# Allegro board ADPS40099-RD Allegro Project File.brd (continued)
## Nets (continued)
UNNAMED_3_ADMAX77857_I197_BST1: C17.2(N2) U3.A3
UNNAMED_3_ADMAX77857_I197_BST2: C21.1 U3.E3
UNNAMED_3_ADMAX77857_I197_EN1: P17.2 U3.B2 U3.B3
UNNAMED_3_ADMAX77857_I197_IN1: C84.1 C85.1 IN_U3.1(N1) P35.1 R76.1 U3.A4 U3.A5 U3.A6 U3.B4
UNNAMED_3_ADMAX77857_I197_LX11: C17.1 L1.2(N2) U3.A7 U3.B5 U3.B6 U3.B7
UNNAMED_3_ADMAX77857_I197_POKB: R27.2(N2) U3.C2
UNNAMED_3_ADMAX77857_I197_SEL: R77.1 U3.D1
UNNAMED_3_CN3P_I185_N1: P17.1 R76.2(N2)
UNNAMED_5_ADLTC3621V2_I158_FB: C107.2(N2) R91.1 R92.1 R102.2(N2) U9.5
UNNAMED_5_ADLTC3621V2_I158_INTVCC: C106.1 P41.2(N2) R99.2(N2) R100.1 U9.6
UNNAMED_5_ADLTC3621V2_I158_PGOOD: R99.1 U9.4
UNNAMED_5_ADLTC3621V2_I158_RUN: P39.2 U9.3
UNNAMED_5_ADLTC3621V2_I158_SW: L8.1 U9.1
UNNAMED_5_ADMAX1722X_I186_EN: R103.2(N2) U10.6
UNNAMED_5_ADMAX1722X_I186_LX: L9.2(N2) U10.2
UNNAMED_5_ADMAX1722X_I186_SEL: R45.1 U10.4(SEL)
UNNAMED_5_ADMAX38889_I125_BKB: R95.1 U5.4
UNNAMED_5_ADMAX38889_I125_CAP: C73.P C74.1 L7.1 R51.1 U5.2 U5.5 VCAP.1(N1)
UNNAMED_5_ADMAX38889_I125_FBCH: C88.1 R52.2(N2) R53.1 U5.10
UNNAMED_5_ADMAX38889_I125_FBCR: R51.2(N2) R52.1 U5.9
UNNAMED_5_ADMAX38889_I125_FBS: R71.2(N2) R72.1 U5.11
UNNAMED_5_ADMAX38889_I125_ISET: R57.1 U5.12
UNNAMED_5_ADMAX38889_I125_LX1: L7.2(N2) U5.6 U5.7 U5.8
UNNAMED_5_ADMAX38889_I125_RDY: R97.2(N2) RDY.1(N1) U5.3
UNNAMED_5_CAP_I104_N1: C91.1 C92.1 C97.1 C98.1 C105.1 P19.2(N2) R69.1 R71.1 R96.1 R97.1 U5.13 U5.14(SYS_2)
UNNAMED_5_CAP_I119_N1: BKB.1(N1) C76.1 R95.2(N2) R96.2(N2)
UNNAMED_5_CN2P_I181_N1: C95.1 L9.1 P46.1 P48.2(N2) P49.2(N2) R103.1 U10.5
UNNAMED_5_NC2P_I157_N1: P38.1 R92.2(N2)
UNNAMED_5_NC2P_I163_N1: P41.1 P42.2(N2) R100.2(N2) R101.1 U9.7
UNNAMED_5_NC2P_I176_N1: P28.1 R91.2(N2)
UNNAMED_5_RES_I103_N2: R69.2(N2) R98.1
UNNAMED_6_CAP_I13_N2: C117.2(N2) R117.1 U14.7(WP)
UNNAMED_6_IC24XX32AV2_I1_A0: R111.2(N2) R112.1 U14.1
UNNAMED_6_IC24XX32AV2_I1_A1: R109.2(N2) R110.1 U14.2
UNNAMED_6_IC24XX32AV2_I1_A2: R61.2(N2) R62.1 U14.3
UNNAMED_6_IC24XX32AV2_I1_SCL: R113.1 U14.6
UNNAMED_6_IC24XX32AV2_I1_SDA: R114.1 U14.5
VCIN: C8.1 P50.2(N2) U2.A5
VIO: C13.1 P21.2(N2) R3.1 R4.1 R9.2(N2) R10.2(N2) R13.2(N2) R14.2(N2) R18.1 R19.1 U7.5 VIO.1(N1)
VIO1: C5.1 P22.2(N2) R25.1 R58.1 R63.2(N2) U2.B1
VIO2: C6.1 P23.2(N2) R5.1 R8.1 U2.C1(VIO2)
VIO3: C86.1 P17.3(N3) P18.1 P24.2(N2) R27.1 R78.1 R80.1 U3.A2
VIO4: P27.2 R34.2(N2)
VIO6: C75.1 P29.2(N2) R15.2(N2) R47.2(N2) R56.1 R59.2(N2) R60.2(N2) R70.2(N2) R85.2(N2) U6.A6
VIO8: C15.1 P25.2(N2) P26.2(N2) P36.2(N2) R21.1 R22.1 R24.2(N2) R28.1 R64.1
VIO9: C117.1 P47.2
VL: C18.1 P18.2(N2) U3.C1(VL)
VSYS: C30.1 C31.1 L2.2(N2) P12.2(N2) P19.1 P31.1 P32.1 P33.1 P34.1 P35.2(N2) P46.2(N2) R29.1 U5.1 U8.E5 U8.F4 U8.F5 U8.G4 U8.G5 VSYS.1(N1)
W1: P14.1 TP21.1(N1)

Pads without a net: D1 2; M1 A2 A3 A8 A10 A11 B2 B3 B8 B10 B11; P15 1 3 5 7 9 10 11 12 13 14 15 16 17 18; S1 1 3; U13 4 5 6 8 9 11

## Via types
v1: diameter 0.508, hole 0.254, TOP to BOTTOM, 885 vias
v2: diameter 0.254, hole 0.127, TOP to L2_GND, 167 vias
v3: diameter 0.254, hole 0.127, TOP to BOTTOM, 51 vias
v4: diameter 0.508, hole 0.257, TOP to BOTTOM, 17 vias

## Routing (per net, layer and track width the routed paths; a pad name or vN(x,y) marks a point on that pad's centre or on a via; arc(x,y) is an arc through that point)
0V9: length 2
  TOP w0.508: C72.1 v1(105.66,27.05)
  BOTTOM w0.508: v1(105.66,27.05) 105.7,27.01 R43.1
1V2: length 1
  BOTTOM w0.508: v1(74.93,27.05) 74.89,27.01 R41.1
  vias: v1(74.93,30.1) v1(74.93,29.34) v1(74.93,28.57) v1(74.93,27.81) v1(75.69,30.1) v1(75.69,29.34) v1(75.69,28.57) v1(75.69,27.81) v1(75.69,27.05) v1(76.45,30.1) v1(76.45,29.34) v1(76.45,28.57) v1(76.45,27.81) v1(76.45,27.05) v1(77.22,30.1) v1(77.22,29.34) v1(77.22,28.57) v1(77.22,27.81) v1(77.22,27.05) v1(77.98,30.1) v1(77.98,29.34) v1(77.98,28.57) v1(77.98,27.81) v1(77.98,27.05)
1V8: length 1
  BOTTOM w0.508: v1(74.93,13.21) 74.89,13.25 R40.1
1V8_VIO: length 13.3
  TOP w0.203: v1(20.59,26.22) 20.39,26.02 U13.3 ; 16.24,27.43 16.24,27.02 16.44,26.82 U13.10
  TOP w0.381: 16.24,27.43 16.24,28.81 16.64,29.21 C101.1
  TOP w0.508: R88.1 v1(21.59,28.7) ; C101.1 17.61,31.28 P23.1 ; C108.1 53.31,11.34 L8.2 ; R89.1 v1(22.63,23.04)
  vias: v1(55.25,9.91) v1(55.25,9.14) v1(55.25,8.38) v1(56.01,9.91) v1(56.01,9.14) v1(56.01,8.38) v1(56.77,9.91) v1(56.77,9.14) v1(56.77,8.38)
3V3: length 2
  TOP w0.508: C69.1 v1(105.66,13.34)
  BOTTOM w0.508: R38.1 105.7,13.37 v1(105.66,13.34)
5V0: length 26.7
  TOP w0.229: U3.D4 U3.E4 U3.E5 U3.E6
  BOTTOM w0.508: R82.2 v1(103.25,47.24) v1(103.25,48.01) ; v1(99.7,47.24) 99.7,48.77 100.71,49.78 104.78,49.78 106.05,51.05 106.05,60.48 P14.14
  vias: v1(97.03,46.48) v1(97.79,47.24) v1(97.79,46.48) v1(98.93,47.24) v1(98.93,46.48) v1(99.7,46.48) v1(101.35,47.24) v1(101.35,46.48) v1(102.11,47.24) v1(102.11,46.48) v1(103.25,48.77) v1(104.01,48.77) v1(104.01,48.01) v1(104.01,47.24) v1(104.78,48.77) v1(104.78,48.01) v1(104.78,47.24) v1(104.78,46.48) v1(105.54,48.77) v1(105.54,48.01) v1(105.54,47.24) v1(105.54,46.48) v1(106.3,48.77) v1(106.3,48.01) v1(106.3,47.24) v1(106.3,46.48)
5V0_VIO:
  vias: v1(36.83,26.67) v1(36.83,25.15) v1(38.35,25.15)
12V0: length 1.6
  TOP w0.229: U1.A4 U1.A5 U1.B5 U1.C5 U1.D5
AGND: length 801
  TOP w0.152: C14.2 54.08,52.46 53.98,52.36 v1(53.98,52.27)
  TOP w0.203: U13.7 v1(19.88,28.19) ; v1(37.97,58.42) 37.54,57.98 U1.E4
  TOP w0.229: C38.2 93.63,20.39 U6.F6 ; U6.F1 92.05,18.39 92.08,18.41 ; 88.77,18.8 88.78,18.79 U6.A2 ; v1(72.14,70.99) 71.95,70.81 R33.2 ; U3.E2 96.3,45.43 97.47,44.26 ; U6.F9 91.82,21.59 91.82,21.59 ; 88.77,21.59 88.78,21.59 U6.A9 ; 92.08,21.97 92.05,21.99 U6.F10 ; 71.95,69.53 72.73,68.75 U4.6 ; U3.D2 v3(95.52,45.83) U3.C3 v3(95.12,46.23) U3.C5 U3.C6 U3.C7 v1(95.12,48.13) 95.12,49.78 ; U6.A1 88.54,18.39 88.52,18.41 ; U6.A10 88.54,21.99 88.52,21.97 ; U6.F2 91.82,18.79 91.82,18.8
  TOP w0.254: U2.D6 36.66,37.73 v1(36.7,37.68)
  TOP w0.305: U5.15 60.46,19.05 59.94,18.54 ; v1(10.06,45.54) 10.06,45.16 9.74,44.84 M1.A1 8.53,44.84 8.28,45.09 M1.B12 v1(7.05,45.09) ; v1(7.05,39.59) M1.B1 8.6,39.59 8.85,39.34 M1.A12 9.86,39.34 10.29,38.92 v1(10.29,38.79) ; v1(21.59,10.79) 21.34,10.54 U14.4
  TOP w0.356: U10.3 v1(34.28,23.77)
  TOP w0.381: GNDC.1 55.65,2.54 ; GNDC.1 53.57,2.54 ; GNDC.1 54.61,1.5 ; GNDC.1 54.61,3.58 ; 63.11,9.91 C73.N ; C73.N 65.07,9.91 ; C73.N 64.09,10.88 ; C73.N 64.09,8.93 ; U9.8 46.7,9.99 v1(47.46,9.99) ; 46.35,51.68 R11.2 46.35,52.97 ; 15.85,2.54 GND6.1 ; GND6.1 16.89,3.58 ; GND6.1 17.93,2.54 ; GND6.1 16.89,1.5 ; P47.3 27.78,14.37 ; P47.3 26.67,15.48 ; P47.3 25.56,14.37 ; P47.3 26.67,13.27 ; 46.35,54.72 R7.1 46.35,56.02 ; 46.35,60.95 R12.2 46.35,62.24 ; 46.35,57.9 R6.1 46.35,59.2 ; 51.68,16.45 P39.3 ; P39.3 50.57,17.55 ; P39.3 51.68,18.66 ; P39.3 52.78,17.55 ; P15.6 13.08,24.92 ; P15.6 14.12,23.88 ; P15.6 13.08,22.83 ; D2.A 98.37,58.01
  TOP w0.508: R12.2 v1(47.12,61.59) ; v1(39.85,41.82) C4.2 v1(37.82,41.82) ; v1(38.1,18.29) 37.02,18.29 C95.2 ; R117.2 v1(15.72,17.64) ; R11.2 v1(47.12,52.32) ; v1(15.75,11.28) C116.2 v1(14.76,12.27) ; C103.2 v1(40.51,37.05) ; P9.1 v1(77.22,60.35) ; C19.2 v1(59.05,59.84) ; RT1.2 v1(54.74,63.98) ; R6.1 v1(47.12,58.55) ; 28.32,40.01 28.32,39.47 v1(27.97,39.12) ; C5.2 29.32,37.93 29.03,37.64 ; R98.2 v1(54.61,30.1) ; C11.2 36.87,36.03 v1(36.7,36.2) ; R7.1 v1(47.12,55.37) ; C86.2 92.48,42.55 C18.2 93.56,41.44 94.23,40.77 96.9,40.77 v1(97.66,41.53) v1(98.39,41.53) R77.2 98.39,43.35 97.47,44.26 ; R20.2 v1(57.91,63.78) ; R72.2 v1(59.98,27.05) ; C102.2 v1(20.19,23.62) ; v1(10.29,38.79) v1(10.29,38.03) ; C37.2 v1(95.25,20.99) C38.2 ; C75.2 v1(83.69,21.08) ; v1(10.06,46.26) v1(10.06,45.54) ; C16.2 v1(56.36,63.88) ; C10.2 v1(32.26,44.58) ; C101.2 v1(20.24,29.21) ; C15.2 v1(55.25,41.71)
  TOP w0.635: v1(53.09,15.05) 53.09,13.53 C108.2 54.1,13.53 ; 54.1,13.53 C109.2 ; 54.1,13.53 v1(54.1,15.05) ; 49.78,20.19 48.33,20.19 C89.2 48.33,21.08 49.78,21.08 ; 50.17,18.67 48.81,18.67 C90.2 48.81,16.64 50.17,16.64
  L2_GND w0.152: v2(34.16,37.73) 34.16,37.72 34.42,37.47 34.42,36.2 v1(38.73,31.88)
  L2_GND w0.381: P47.3 26.67,15.48 ; P47.3 27.78,14.37 ; P47.3 25.56,14.37 ; P47.3 26.67,13.27 ; 54.61,1.5 GNDC.1 ; GNDC.1 53.57,2.54 ; GNDC.1 55.65,2.54 ; GNDC.1 54.61,3.58 ; GND6.1 17.93,2.54 ; GND6.1 15.85,2.54 ; GND6.1 16.89,1.5 ; GND6.1 16.89,3.58 ; P15.6 13.08,24.92 ; P15.6 12.04,23.88 ; P15.6 14.12,23.88 ; P15.6 13.08,22.83 ; C73.N 64.09,10.88 ; C73.N 65.07,9.91 ; C73.N 64.09,8.93 ; C73.N 63.11,9.91 ; P39.3 51.68,18.66 ; P39.3 52.78,17.55 ; P39.3 50.57,17.55 ; P39.3 51.68,16.45
  L3_SIG w0.203: 79.5,64.01 79.5,61.98 80.39,61.09 v1(80.39,58.8) v1(80.39,51.18) 78.49,49.28 v1(78.49,47.5) 80.26,45.72 87.63,45.72 88.77,46.86 91.06,46.86 93.98,43.94 93.98,43.31 ; 79.5,64.01 78.74,64.01 75.69,67.06 71.37,67.06 69.85,65.53 65.53,65.53 ; 79.5,64.01 79.5,68.33 78.49,69.34 66.8,69.34 65.53,68.07 65.53,65.53 ; v1(55.25,41.71) 56.56,40.39 72.14,40.39 74.17,42.42 74.17,51.05 69.34,55.88 69.34,59.18 65.91,62.61 v1(65.91,63.5) 66.93,64.52 70.36,64.52 71.88,66.04 75.18,66.04 78.49,62.74 78.49,61.47 79.25,60.71 v1(79.25,53.34) 79.25,51.56 77.22,49.53 77.22,47.24 79.91,44.55 v1(85.52,44.55) ; v1(64.29,66.6) 64.29,68.61 66.04,70.36 78.99,70.36 80.52,68.83 80.52,62.48 81.79,61.21 81.79,51.14 79.76,49.11 79.76,47.72 80.99,46.48 87.12,46.48 88.39,47.75 91.69,47.75 96.27,43.18 97.03,43.18 97.66,42.55 v1(97.66,41.53) ; 65.53,65.53 65.53,64.77 63.75,62.99 63.75,62.48 66.17,60.07 v1(66.85,60.07) 68.33,58.6 68.33,55.37 73.28,50.42 73.28,43.05 71.37,41.15 57.4,41.15 54.99,43.56 54.99,48.26 54.86,48.39 53.72,48.39
  L3_SIG w0.254: v3(59.72,52.5) v3(59.72,52.9) 59.72,53.84 59.64,53.92 ; v1(44.45,64.26) 44.45,65.15 ; 89.41,20.45 89.46,20.39 v3(90.1,20.39) ; v1(23.4,25.4) 23.9,25.91 30.61,25.91 32.13,24.38 32.13,23.49
  L3_SIG w0.381: 26.67,13.27 P47.3 ; P47.3 26.67,15.48 ; P47.3 25.56,14.37 ; 64.09,8.93 C73.N ; C73.N 63.11,9.91 ; C73.N 64.09,10.88 ; C73.N 65.07,9.91 ; GND3.1 72.8,2.54 ; GND3.1 71.75,1.5 ; GND3.1 71.75,3.58 ; GND3.1 70.71,2.54 ; 110.72,22.73 GND4.1 ; GND4.1 112.8,22.73 ; GND4.1 111.76,23.77 ; GND4.1 111.76,21.69 ; 54.61,1.5 GNDC.1 ; GNDC.1 53.57,2.54 ; GNDC.1 54.61,3.58 ; GNDC.1 55.65,2.54 ; 12.04,23.88 P15.6 ; P15.6 13.08,24.92 ; P15.6 13.08,22.83 ; 110.72,36.7 GND5.1 ; GND5.1 111.76,35.66 ; GND5.1 111.76,37.74 ; GND5.1 112.8,36.7 ; GND1.1 106.05,3.58 ; GND1.1 105,2.54 ; GND1.1 106.05,1.5 ; GND1.1 107.09,2.54 ; GND2.1 95.66,2.54 ; GND2.1 93.57,2.54 ; GND2.1 94.62,3.58 ; GND2.1 94.62,1.5
  L3_SIG w0.508: v1(35.31,44.58) 34.29,44.58 ; v1(37.82,41.82) 37.82,40.92 37.85,40.89 ; v1(36.83,43.18) 36.58,42.93
  L4_PWR w0.381: GND5.1 112.8,36.7 ; GND5.1 111.76,37.74 ; GND5.1 111.76,35.66 ; GND5.1 110.72,36.7 ; GND3.1 71.75,3.58 ; GND3.1 72.8,2.54 ; GND3.1 70.71,2.54 ; GND3.1 71.75,1.5 ; 50.57,17.55 P39.3 ; P39.3 52.78,17.55 ; P39.3 51.68,18.66 ; 106.05,1.5 GND1.1 ; GND1.1 105,2.54 ; GND1.1 107.09,2.54 ; GND1.1 106.05,3.58 ; GNDC.1 55.65,2.54 ; GNDC.1 53.57,2.54 ; GNDC.1 54.61,3.58 ; GNDC.1 54.61,1.5 ; 26.67,13.27 P47.3 ; P47.3 27.78,14.37 ; P47.3 25.56,14.37 ; GND4.1 112.8,22.73 ; GND4.1 111.76,21.69 ; GND4.1 110.72,22.73 ; GND4.1 111.76,23.77 ; GND6.1 17.93,2.54 ; GND6.1 16.89,1.5 ; GND6.1 16.89,3.58 ; GND6.1 15.85,2.54 ; C73.N 65.07,9.91 ; C73.N 64.09,8.93 ; C73.N 64.09,10.88 ; C73.N 63.11,9.91 ; 13.08,22.83 P15.6 ; P15.6 12.04,23.88 ; P15.6 13.08,24.92 ; 93.57,2.54 GND2.1 ; GND2.1 94.62,1.5 ; GND2.1 94.62,3.58 ; GND2.1 95.66,2.54
  L4_PWR w0.508: 83.49,20.37 82.93,19.81 v1(82.93,19.3) 82.93,18.8 83.44,18.29
  L5_GND w0.254: 89.59,20.4 89.59,20.39 v3(90.1,20.39)
  L5_GND w0.381: P15.6 14.12,23.88 ; P15.6 12.04,23.88 ; P15.6 13.08,22.83 ; P15.6 13.08,24.92 ; 25.56,14.37 P47.3 ; P47.3 26.67,13.27 ; P47.3 27.78,14.37 ; P47.3 26.67,15.48 ; 63.11,9.91 C73.N ; C73.N 64.09,8.93 ; C73.N 64.09,10.88 ; C73.N 65.07,9.91 ; GNDC.1 54.61,3.58 ; GNDC.1 55.65,2.54 ; GNDC.1 54.61,1.5 ; GNDC.1 53.57,2.54 ; 16.89,1.5 GND6.1 ; GND6.1 17.93,2.54 ; GND6.1 16.89,3.58 ; GND6.1 15.85,2.54 ; 50.57,17.55 P39.3 ; P39.3 51.68,18.66 ; P39.3 52.78,17.55 ; P39.3 51.68,16.45
  BOTTOM w0.203: v1(57.18,47.85) 56.62,47.85 56.13,47.37 56.13,42.59 v1(55.25,41.71)
  BOTTOM w0.254: v3(59.72,52.5) v3(59.72,52.9) 59.72,53.68 59.74,53.7 ; v3(34.66,38.23) 35.14,38.23 C9.2 ; TP19.1 v1(41.53,32.77)
  BOTTOM w0.305: C76.2 v1(63.63,16)
  BOTTOM w0.356: v1(34.28,23.77) 35.5,23.77 R45.2
  BOTTOM w0.381: 51.68,16.45 P39.3 ; P39.3 50.57,17.55 ; P39.3 51.68,18.66 ; P39.3 52.78,17.55 ; 40.16,7.75 P38.2 40.74,8.8 ; v1(27.97,39.12) v1(20.83,39.12) v1(16.79,43.15) v1(11.55,43.15) ; 43.17,56.25 R1.2 42.49,57.02 ; 53.57,2.54 GNDC.1 ; GNDC.1 55.65,2.54 ; GNDC.1 54.61,3.58 ; GNDC.1 54.61,1.5 ; 39.73,69.72 C13.2 40.47,68.95 ; 92.84,38.3 R81.2 93.61,37.63 ; 71.75,1.5 GND3.1 ; GND3.1 72.8,2.54 ; GND3.1 71.75,3.58 ; GND3.1 70.71,2.54 ; 13.08,22.83 P15.6 ; P15.6 12.04,23.88 ; P15.6 13.08,24.92 ; 111.76,21.69 GND4.1 ; GND4.1 112.8,22.73 ; GND4.1 111.76,23.77 ; GND4.1 110.72,22.73 ; D4.A 65.05,61.1 ; D4.A 64.54,60.4 ; D4.A 65.56,60.4 ; GND2.1 95.66,2.54 ; GND2.1 93.57,2.54 ; GND2.1 94.62,3.58 ; GND2.1 94.62,1.5 ; 50.62,14.07 P42.1 ; P42.1 51.68,14.66 ; P42.1 52.73,14.07 ; 63.37,21.54 R53.2 62.6,20.87 ; GND6.1 17.93,2.54 ; GND6.1 16.89,1.5 ; GND6.1 16.89,3.58 ; GND6.1 15.85,2.54 ; 43.17,59.32 R2.2 42.49,58.55 ; R84.2 98.44,42.46 ; R84.2 97.66,43.13 ; R84.2 96.89,42.46 ; R45.2 36.34,23.71 ; R45.2 35.56,24.38 ; R45.2 34.78,23.71 ; R45.2 35.56,23.04 ; R101.2 50.55,14.92 ; R101.2 49.77,14.25 ; R101.2 49,14.92 ; R101.2 49.77,15.6 ; GND1.1 106.05,3.58 ; GND1.1 107.09,2.54 ; GND1.1 105,2.54 ; GND1.1 106.05,1.5 ; 74.22,24.51 R42.1 75.56,24.51 ; C106.2 44.79,11.44 ; C106.2 44.04,10.67 ; C106.2 44.79,9.89 ; C106.2 45.54,10.67 ; 65.05,65.9 D3.A ; D3.A 64.54,66.6 ; D3.A 65.05,67.29 ; D3.A 65.56,66.6 ; C93.2 66.85,66.68 ; C93.2 67.63,65.93 ; C93.2 66.08,65.93 ; 40.16,5.46 P28.2 40.74,4.41 ; 96.61,15.35 R46.2 ; R46.2 97.28,16.13 ; R46.2 95.93,16.13 ; OUT-.1 106.32,38.99 ; OUT-.1 105.54,38.2 ; OUT-.1 105.54,39.78 ; C94.2 v1(66.85,60.07) ; C94.2 67.63,61.07 ; C94.2 66.08,61.07 ; C48.2 96.35,58.79 ; C48.2 97.1,58.01 ; C48.2 96.35,57.24 ; 84.62,23.64 R50.2 85.29,22.86 ; R55.2 97.28,24.26 ; R55.2 95.93,24.26 ; R55.2 96.61,25.03 ; 42.8,31.98 TP19.1 ; TP19.1 43.59,32.77 ; TP19.1 42.8,33.55 ; U7.2 v1(44.45,64.26) ; 61.44,21.24 C88.2 ; C88.2 62.51,21.24 ; C88.2 61.98,20.68 ; 105.03,15.88 R39.1 106.38,15.88 ; 26.67,13.27 P47.3 ; P47.3 27.78,14.37 ; P47.3 26.67,15.48 ; P47.3 25.56,14.37 ; 85.29,17.78 R48.2 84.62,17 ; 20.32,9.19 R62.2 21.1,9.87
  BOTTOM w0.508: v1(74.93,23.49) 74.89,23.53 R42.1 ; 67.18,25.53 67.18,23.28 70.83,19.63 v1(72.62,19.63) v1(77.75,19.63) ; P14.11 P14.12 ; P14.11 P14.9 P14.7 ; P14.11 P14.13 P14.15 ; v1(99.7,52.32) v1(99.7,51.56) 99.7,50.93 100.08,50.55 104.14,50.55 105.16,51.56 105.16,61.59 P14.16 ; v1(99.19,19.18) R49.1 98.13,19.01 96.77,17.65 C46.2 96.61,17.6 R46.2 ; R39.1 105.7,16.85 v1(105.66,16.89) ; R48.2 83.95,17.78 82.93,18.8 v1(82.93,19.3) ; P14.8 P14.7 ; P14.7 P14.5 P14.3 112.6,54.07 112.93,53.75 112.93,50.83 109.35,47.24 109.35,42.8 OUT-.1 100.93,38.99 v1(98.39,41.53) v1(97.66,41.53) R84.2 ; R2.2 43.94,58.55 44.2,58.29 v1(44.2,57.79) 44.2,57.28 43.94,57.02 R1.2 ; P38.2 P28.2 ; R110.2 v1(18.8,10.79) ; C13.2 40.47,70.99 ; v1(82.17,21.34) 83.69,22.86 R50.2 ; R62.2 v1(20.32,10.79) ; R81.2 v1(92.84,36.7) ; R54.1 v1(83.69,21.08) ; R55.2 96.61,22.78 C43.2 96.77,22.73 98.08,21.42 C32.2 v1(99.19,21.21) ; v1(36.7,37.68) C9.2 ; R79.2 v1(91.06,36.7) ; R32.2 v1(69.72,67.69) ; R112.2 v1(17.27,10.79)
  BOTTOM w0.635: R53.2 63.37,19.3 ; P15.6 14.48,23.88
  vias: v1(1.27,74.8) v1(1.27,69.09) v1(1.27,63.37) v1(1.27,57.66) v1(1.27,51.94) v1(1.27,34.8) v1(1.27,29.08) v1(1.27,23.37) v1(1.27,17.65) v1(1.27,11.94) v1(1.27,6.22) v1(3.81,54.61) v1(3.81,53.34) v1(3.81,52.07) v1(3.81,50.8) v1(5.08,54.61) v1(5.08,53.34) v1(5.08,52.07) v1(6.35,54.61) v1(6.35,53.34) v1(6.35,1.27) v1(7.62,57.15) v1(7.62,55.88) v1(7.62,54.61) v1(7.62,53.34) v1(8.26,74.8) v1(8.89,57.15) v1(8.89,55.88) v1(8.89,54.61) v1(8.89,53.34) v1(8.89,52.07) v1(8.89,50.8) v1(10.16,54.61) v1(10.16,53.34) v1(10.16,52.07) v1(10.16,50.8) v1(10.92,40.95) v1(11.43,54.61) v1(11.43,53.34) v1(11.43,1.27) v1(12.7,64.77) v1(12.7,54.61) v1(12.7,53.34) v1(13.84,31.24) v1(13.97,74.8) v1(15.49,40.89) v1(16.13,20.7) v1(16.13,5.71) v1(16.51,60.96) v1(17.53,38.99) v1(19.18,18.67) v1(19.56,36.83) v1(19.68,74.8) v1(20.32,64.77) v1(20.32,57.15) v1(20.32,45.72) v1(20.83,18.72) v1(22.61,35.56) v1(23.49,23.24) v1(24,36.83) v1(24.13,60.96) v1(24.13,49.53) v1(24.13,41.91) v1(25.02,4.7) v1(25.4,34.29) v1(26.67,1.27) v1(27.94,45.72) v1(27.97,36.83) v1(28.19,61.21) v1(28.19,60.45) v1(28.19,59.69) v1(28.19,58.93) v1(28.19,58.17) v1(28.19,57.4) v1(28.19,56.64) v1(28.19,55.88) v1(28.19,55.12) v1(28.19,54.36) v1(28.96,61.21) v1(28.96,60.45) v1(28.96,59.69) v1(28.96,58.93) v1(28.96,58.17) v1(28.96,57.4) v1(28.96,56.64) v1(28.96,55.88) v1(28.96,55.12) v1(28.96,54.36) v1(29.72,61.21) v1(29.72,60.45) v1(29.72,59.69) v1(29.72,55.88) v1(29.72,55.12) v1(29.72,54.36) v1(30.07,33.76) v1(31.11,5.97) v1(31.11,4.7) v1(31.37,36.32) v1(31.67,33.76) v1(31.75,1.27) v1(34.14,33.76) v1(35.92,51.18) v1(36.07,44.58) v1(36.83,1.27) v1(38.1,20.83) v1(38.1,19.56) v1(38.23,47.75) v1(38.73,33.78) v1(38.73,3.81) v1(39.24,71.25) v1(39.24,54.61) v1(39.5,64.52) v1(39.5,63.75) v1(39.5,62.99) v1(39.5,60.71) v1(39.88,7.75) v1(39.88,5.71) v1(40.01,3.81) v1(40.01,2.54) v1(40.26,64.52) v1(40.26,63.75) v1(40.26,62.99) v1(40.26,60.71) v1(40.51,55.37) v1(40.51,51.18) v1(40.77,9.14) v1(41.02,64.52) v1(41.02,63.75) v1(41.02,62.99) v1(41.02,62.23) v1(41.02,61.47) v1(41.02,60.71) v1(41.28,3.81) v1(41.28,2.54) v1(41.53,74.42) v1(41.53,33.78) v1(42.16,63.88) v1(42.55,3.81) v1(42.67,61.09) v1(43.05,15.24) v1(43.78,10.67) v1(43.94,40.13) v1(44.45,74.42) v1(44.45,72.01) v1(45.59,51.18) v1(46.99,47.75) v1(47.24,74.42) v1(47.24,71.12) v1(47.62,49.15) v1(48.9,62.61) v1(48.9,58.04) v1(49.53,50.93) v1(50.16,20.83) v1(50.16,19.18) v1(50.16,17.91) v1(50.16,16.64) v1(53.09,56.85) v1(53.09,54.46) v1(53.26,52.98) v1(53.26,52.27) v1(53.43,24.26) v1(53.43,22.61) v1(53.43,21.08) v1(53.43,19.56) v1(53.59,47.75) v1(53.98,52.98) v1(54.1,67.69) v1(54.64,34.14) v1(55.5,15.05) v1(55.55,1.32) v1(55.91,52.98) v1(55.91,52.27) v1(56.52,15.05) v1(57.66,43.69) v1(58.8,17.65) v1(59.05,55.5) v1(59.56,16.89) v1(59.82,18.8) v1(60.3,44.88) v1(60.3,42.29) v1(61.01,44.88) v1(61.01,42.29) v1(61.09,67.69) v1(61.09,21.75) v1(61.09,20.86) v1(61.7,59.99) v1(61.72,59.28) v1(62.41,60.02) v1(62.43,59.31) v1(62.89,48.77) v1(63.12,60.05) v1(63.14,59.33) v1(63.6,48.77) v1(64.21,1.45) v1(64.29,60.4) v1(64.31,48.77) v1(65.02,48.77) v1(65,36.25) v1(65.74,48.77) v1(66.45,48.77) v1(66.75,38.25) v1(66.85,66.95) v1(67.06,15.24) v1(67.16,48.77) v1(67.87,48.77) v1(67.92,32.26) v1(68.33,62.1) v1(68.58,48.77) v1(68.71,31.22) v1(69.32,29.87) v1(70.38,23.09) v1(70.48,1.4) v1(70.61,71.75) v1(70.61,70.99) v1(70.87,21.08) v1(71.09,33.3) v1(71.37,71.75) v1(71.37,70.99) v1(71.7,38.43) v1(72.14,71.75) v1(72.26,27.43) v1(72.31,15.62) v1(72.87,10.9) v1(72.87,6.27) v1(73.38,36.6) v1(73.38,35.84) v1(74.14,36.6) v1(74.14,35.84) v1(74.93,22.73) v1(74.93,17.65) v1(74.93,16.89) v1(76.45,23.49) v1(76.45,22.73) v1(76.45,17.65) v1(76.45,16.89) v1(76.71,51.05) v1(76.68,36.6) v1(76.68,35.84) v1(77.44,36.6) v1(77.44,35.84) v1(77.98,23.49) v1(77.98,22.73) v1(77.98,17.65) v1(77.98,16.89) v1(78.49,60.33) v1(79.5,23.49) v1(79.5,22.73) v1(79.5,17.65) v1(79.5,16.89) v1(79.68,21.08) v1(79.98,36.6) v1(79.98,35.84) v1(80.75,36.6) v1(80.75,35.84) v1(81.03,23.49) v1(81.03,22.73) v1(81.03,17.65) v1(81.03,16.89) v1(81.15,63.12) v1(82.55,23.49) v1(82.55,22.73) v1(82.55,17.65) v1(82.55,16.89) v1(83.06,62.61) v1(83.29,36.6) v1(83.29,35.84) v1(83.95,26.92) v1(83.95,26.16) v1(83.95,25.4) v1(83.95,14.99) v1(83.95,14.22) v1(83.95,13.46) v1(84.05,36.6) v1(84.05,35.84) v1(85.52,43.15) v1(86.11,5.59) v1(86.49,68.2) v1(88.14,52.32) v1(88.14,51.56) v1(88.65,62.36) v1(88.9,52.32) v1(88.9,51.56) v1(89.41,42.55) v1(89.66,64.9) v1(89.79,52.32) v1(89.79,51.56) v1(90.55,52.32) v1(90.55,51.56) v1(91.19,5.59) v1(91.19,1.4) v1(92.2,35.43) v1(92.46,67.44) v1(94.74,48.77) v1(95,56.49) v1(95,55.78) v1(95.5,48.77) v1(95.76,67.44) v1(95.71,56.49) v1(95.71,55.78) v1(96.27,5.59) v1(96.65,26.92) v1(96.65,26.16) v1(96.65,25.4) v1(96.65,14.99) v1(96.65,14.22) v1(96.65,13.46) v1(98.04,23.49) v1(98.04,22.73) v1(98.04,17.65) v1(98.04,16.89) v1(98.35,58.37) v1(98.35,57.66) v1(98.93,35.43) v1(99.06,58.37) v1(99.06,57.66) v1(99.57,23.49) v1(99.57,22.73) v1(99.57,17.65) v1(99.57,16.89) v1(100.46,52.32) v1(100.46,51.56) v1(100.84,68.71) v1(101.09,23.49) v1(101.09,22.73) v1(101.09,17.65) v1(101.09,16.89) v1(101.35,52.32) v1(101.35,51.56) v1(102.11,52.32) v1(102.11,51.56) v1(102.62,23.49) v1(102.62,22.73) v1(102.62,17.65) v1(102.62,16.89) v1(103.71,55.65) v1(104.14,23.49) v1(104.14,22.73) v1(104.14,17.65) v1(104.14,16.89) v1(104.24,74.8) v1(104.24,69.72) v1(104.24,64.64) v1(105.66,23.49) v1(105.66,22.73) v1(105.66,17.65) v1(107.62,24.26) v1(107.65,21.36) v1(107.59,18.82) v1(107.82,74.8) v1(108.08,35.31) v1(109.32,69.72) v1(109.47,15.16) v1(112.78,69.32) v1(112.9,74.8) v1(112.88,65.05) v1(112.88,63.04) v1(112.88,61.06) v1(112.88,59.08) v1(112.88,57.05) v1(112.88,55.04) v1(112.9,39.78) v1(113.11,49.91) v3(35.41,57.98) v3(35.41,57.59) v3(35.81,57.98) v3(60.92,51.7) v4(17.86,27.3) v4(17.86,26.42) v4(17.86,25.53) v4(18.97,27.3) v4(18.97,26.42) v4(18.97,25.53) v4(45.09,13.08) v4(45.09,12.07) v4(46.36,13.08) v4(46.36,12.07) v4(63.12,19.3)
PVDD: length 20.7
  TOP w0.229: C23.1 62.95,51.7 U8.G3
  TOP w0.508: C23.1 65.2,51.27 v1(65.41,51.07)
  L4_PWR w0.508: v1(65.41,51.07) 63.51,51.07 61.98,49.53 61.98,48.26 59.18,45.47 59.18,40.89 P11.3
VBUS: length 12.4
  TOP w0.229: U1.D2 U1.C2 U1.B2 U1.A2 U1.A3
  TOP w0.254: 37.93,40.26 37.21,40.26 36.18,39.23 U2.A6
  TOP w0.305: v1(10.41,43.87) 10.41,43.61 10.14,43.34 M1.A4 8.78,43.34 8.53,43.59 M1.B9 v1(7.05,43.59) ; 11.18,40.31 10.67,40.31 10.14,40.84 M1.A9 8.74,40.84 v1(8.49,41.09) M1.B4
  vias: v1(10.41,44.58) v1(11.13,46.71) v1(11.13,46) v1(11.13,45.29) v1(11.13,44.58) v1(11.68,40.26) v1(11.68,39.5) v1(11.84,46.71) v1(11.84,46) v1(11.84,45.29) v1(11.84,44.58) v1(12.45,40.26) v1(12.45,39.5) v1(12.55,46.71) v1(12.55,46) v1(12.55,45.29) v1(12.55,44.58) v1(13.21,40.26) v1(13.21,39.5) v1(13.97,40.26) v1(13.97,39.5) v1(30.76,55.12) v1(30.76,54.36) v1(30.76,53.59) v1(30.76,52.83) v1(31.52,55.12) v1(31.52,54.36) v1(31.52,53.59) v1(31.52,52.83) v1(32.28,55.12) v1(32.28,54.36) v1(32.28,53.59) v1(32.28,52.83)
VCC_EXT: length 24.5
  TOP w0.508: v1(17.61,22.54) C102.1 v1(16.54,23.62)
  L4_PWR w0.635: v1(17.61,22.54) 17.61,14.52 19.6,12.53 19.6,9.74 21.34,8 21.34,6.73 20.32,5.71 20.32,3.56 VCC_EXT.1
  vias: v1(28.7,24.64) v1(28.7,23.37) v1(30.48,24.64) v1(30.48,23.37) v1(41.12,20.57) v1(41.12,19.56)
VDD: length 3.2
  TOP w0.229: U6.F5 93.63,19.99 C38.1
VIN_U14: length 11.2
  TOP w0.508: C116.1 v1(14.76,13.87) ; C116.1 v1(15.75,14.86) ; C116.1 16.7,13.87 16.73,13.84 17.53,13.84 ; R115.1 v1(19.02,21.41) ; R116.1 v1(22.63,21.41)
  BOTTOM w0.508: v1(16.17,4.74) R111.1 R109.1 R61.1 v1(21.55,4.74)
AVL: length 2.9
  TOP w0.203: U2.C6 37.25,38.23 C11.1
BATSP: length 13.6
  TOP w0.229: P20.2 60.12,63.7 U8.D7
BATT: length 43.7
  TOP w0.152: U8.G7 U8.G6 U8.F6 ; U8.F6 U8.E6 ; U8.F6 U8.F7
  TOP w1.016: v1(57.18,70.03) v1(56.4,70.03) 56.4,72.99 S2.2
  BOTTOM w0.381: P40.1 70.99,57.37 ; P40.1 70.99,55.16 ; P40.1 69.89,56.26 ; P40.1 72.1,56.26
  BOTTOM w0.508: 53.8,60.12 50.9,57.23 R65.1
  BOTTOM w1.016: v1(64.31,57.3) 59.61,57.3 57.43,59.49 54.43,59.49 53.8,60.12 53.8,64.39 P20.1 55.35,68.98 v1(56.4,70.03) v1(57.18,70.03)
  vias: v1(64.31,56.59) v1(64.31,55.88) v1(64.31,55.17) v1(64.31,54.46) v1(65.02,57.3) v1(65.02,56.59) v1(65.02,55.88) v1(65.02,55.17) v1(65.02,54.46) v1(65.74,57.3) v1(65.74,56.59) v1(65.74,55.88) v1(65.74,55.17) v1(65.74,54.46) v1(66.45,57.3) v1(66.45,56.59) v1(66.45,55.88) v1(66.45,55.17) v1(66.45,54.46) v1(87.55,68.15) v1(87.55,67.44) v1(87.55,66.73) v1(88.27,68.15) v1(88.27,67.44) v1(88.27,66.73) v1(88.75,58.39) v1(88.75,57.68) v1(89.03,56.46) v1(89.03,55.75) v1(89.46,58.39) v1(89.46,57.68) v1(89.74,56.46) v1(89.74,55.75) v1(90.17,58.39) v1(90.17,57.68) v1(90.27,60.99) v1(90.27,60.27) v1(90.45,56.46) v1(90.45,55.75) v1(90.98,60.99) v1(90.98,60.27) v1(91.69,60.99) v1(91.69,60.27)
BATT_N: length 28.5
  TOP w0.203: R31.1 76.2,65.03
  TOP w0.229: 73.85,69.53 73.13,68.81 U4.5 ; R33.1 73.85,70.81 v1(73.66,70.99) ; P2.2 62.33,72.76 62.33,65.61 60.52,63.8 U8.E7
  TOP w0.508: C41.2 v1(70.74,64.14) ; 76.2,65.03 v1(76.2,64.26)
  vias: v1(73.66,71.75) v1(74.42,71.75) v1(74.42,70.99) v1(75.18,71.75) v1(75.18,70.99) v4(72.77,65.15) v4(72.77,64.14) v4(73.53,65.15) v4(73.53,64.14) v4(74.3,65.15) v4(74.3,64.14)
BATT_P: length 78.9
  TOP w0.229: P20.3 61.95,67.46 61.95,72.69 P2.1
  L3_SIG w0.508: v1(41.12,16.5) v1(41.12,17.51) 42.67,19.06 42.67,35.81 49.02,42.16 49.02,49.15 46.46,51.71 46.46,65.51 49.91,68.96 54.48,68.96 55.63,67.82 58.55,67.82 P20.3
  vias: v1(28.7,18.54) v1(28.7,17.27) v1(30.48,18.54) v1(30.48,17.27) v1(78.03,66.55) v1(78.03,65.84) v1(78.74,66.55) v1(78.74,65.84) v1(100.97,62.61) v1(100.97,60.58) v1(101.98,62.61) v1(101.98,61.59) v1(101.98,60.58)
CC1: length 31
  TOP w0.254: v1(33.43,42.75) 33.17,42.49 33.17,40.87 33.66,40.38 U2.A3
  TOP w0.305: v1(11.81,43.82) 11.27,43.82 10.3,42.84 M1.A5
  BOTTOM w0.508: v1(33.43,42.75) 30.58,39.9 21.92,39.9 18.01,43.82 v1(11.81,43.82)
CC2: length 32.2
  TOP w0.254: v1(33.93,41.35) 34.16,41.12 U2.A4
  TOP w0.305: M1.B5 v1(7.05,41.59)
  L3_SIG w0.508: v1(7.05,41.59) 8.51,40.13 9.91,40.13 11.56,38.48 14.73,38.48 17.4,41.15 33.02,41.15 33.22,41.35 v1(33.93,41.35)
CE: length 22.1
  TOP w0.229: v1(87.38,21.46) 88.05,20.79 U6.A7
  BOTTOM w0.203: P3.2 73.41,21.97 80.52,21.97 81.79,20.7 82.55,20.7 83.84,21.99 86.85,21.99 v1(87.38,21.46)
CHGIN:
  vias: v1(53.57,49.94) v1(53.57,49.23) v1(54.28,49.94) v1(54.28,49.23) v1(54.99,49.94) v1(54.99,49.23)
DIS: length 28.2
  TOP w0.381: v1(89.66,64.01) 90.14,63.53 Q2.4
  BOTTOM w0.254: v1(89.66,64.01) 91.19,64.01 93.22,66.04 93.22,68.2 90.3,71.12 86.74,71.12 81.94,66.32 TP32.1 R36.2
DN: length 2.2
  BOTTOM w0.15: v3(32.66,37.73) 31.16,37.73 R16.2
DN_USBC: length 67.3
  TOP w0.15: v1(10.92,41.73) 10.77,41.89 9.46,41.89 M1.A7 ; v1(27.97,37.62) 26.95,38.63 26.95,43.31 33.91,50.27 46.8,50.27 52.38,55.85 52.91,55.85 v1(53.06,56.01) 53.21,55.85 53.46,55.85 R90.1 ; v1(8.51,42.73) 8.37,42.59 M1.B7
  BOTTOM w0.15: v1(8.51,42.73) 8.33,42.55 8,42.55 7.9,42.65 7.9,42.88 8.26,43.23 8.95,43.23 10.3,41.89 10.77,41.89 v1(10.92,41.73) 11.07,41.89 16.08,41.89 20.2,37.77 27.81,37.77 v1(27.97,37.62) 28.12,37.77 28.39,37.77 R16.1 ; R90.1 53.46,55.85 53.21,55.85 v1(53.06,56.01)
DP: length 2.9
  BOTTOM w0.15: R17.2 31.25,38.13 32.75,38.13 v3(33.16,37.73)
DP_USBC: length 67.1
  TOP w0.15: v1(27.97,38.33) 27.36,38.94 27.36,43.14 34.08,49.86 46.96,49.86 52.55,55.45 52.91,55.45 v1(53.06,55.3) 53.21,55.45 53.46,55.45 R26.1 ; M1.A6 9.46,42.29 10.77,42.29 v1(10.92,42.45) ; v1(8.51,41.96) 8.38,42.09 M1.B6
  BOTTOM w0.15: R26.1 53.46,55.45 53.21,55.45 v1(53.06,55.3) ; v1(8.51,41.96) 8.33,42.14 7.83,42.14 7.49,42.48 7.49,43.05 8.09,43.64 9.12,43.64 10.46,42.29 10.77,42.29 v1(10.92,42.45) 11.07,42.29 16.25,42.29 20.37,38.18 27.81,38.18 v1(27.97,38.33) 28.12,38.18 28.39,38.18 R17.1
IN+: length 36.2
  TOP w0.229: U3.E1 v1(96.52,44.43)
  TOP w0.508: P14.10 108.08,60.07 107.57,59.56 107.57,54.61 108.11,54.07 P14.4
  BOTTOM w0.508: v1(96.52,44.43) 96.79,44.16 R84.1 99.32,44.16 C87.2 99.35,44.02 R83.2 99.35,41.87 99.7,41.53 IN+.1 108.33,44.32 108.33,52.77 P14.4
INAOK_N: length 18.9
  TOP w0.203: U1.E1 36.81,56.79 v1(37.21,56.39)
  L3_SIG w0.203: v1(43.8,64.77) 43.42,65.15 39.24,65.15 38.86,64.77 38.86,58.04 v1(37.21,56.39)
  BOTTOM w0.203: U7.3 v1(43.8,64.77) ; v1(37.21,56.39) 37.34,56.26 R9.1
INBOK_N: length 19.5
  TOP w0.203: v1(37.21,59.18) 36.81,58.78 U1.E6
  L3_SIG w0.203: v1(45.1,64.77) 45.1,65.39 44.32,66.17 38.74,66.17 37.85,65.28 37.85,59.82 v1(37.21,59.18)
  BOTTOM w0.203: R10.1 37.34,59.31 v1(37.21,59.18) ; U7.1 v1(45.1,64.77)
LX2: length 11.7
  TOP w0.229: v1(96.9,47.75) v1(96.9,48.51) 96.65,48.51 v1(96.27,48.13) 95.92,47.79 U3.E7 U3.D7 U3.D6 U3.D5
  TOP w0.508: C21.2 v1(100.97,45.34)
  BOTTOM w0.508: v1(100.97,45.34) 96.9,45.34 96.27,45.97 v1(96.27,48.13)
  vias: v1(97.31,53.98) v1(97.31,52.71) v1(97.31,51.44) v1(98.2,53.98) v1(98.2,52.71) v1(98.2,51.44)
OUT+: length 27.6
  L3_SIG w0.508: P14.2 107.95,52.07 107.44,52.58 107.44,55.5 108.01,56.07 P14.6
  BOTTOM w0.508: P14.6 107.19,53.62 107.19,45.72 OUT+.1 105.5,44.11 R82.1 103.21,44.07 C87.1 101.05,44.02 R83.1
PCKP: length 47.5
  TOP w0.152: R67.2 v1(93.73,58.01)
  TOP w0.229: v1(73.33,61.87) 73.53,62.08 U4.11
  L4_PWR w0.254: P40.3 73.33,59 v1(73.33,61.87)
  BOTTOM w0.508: v1(73.33,61.87) 73.33,61.65 73.94,61.03 82.47,61.03 83.87,62.43 83.87,66.6 86.67,69.4 88.59,69.4 89.41,68.58 89.41,65.66 88.9,65.15 88.9,63.12 89.41,62.61 91.82,62.61 94.75,59.68 C48.1 v1(93.73,58.01)
PP_VOUT:
  vias: v1(35.43,68.58) v1(35.43,67.82) v1(35.43,67.06) v1(35.43,66.29) v1(35.43,62.74) v1(35.43,61.98) v1(35.43,61.21) v1(35.43,60.45) v1(35.43,55.12) v1(35.43,54.36) v1(35.43,53.59) v1(35.43,52.83) v1(36.2,68.58) v1(36.2,67.82) v1(36.2,67.06) v1(36.2,66.29) v1(36.2,62.74) v1(36.2,61.98) v1(36.2,61.21) v1(36.2,60.45) v1(36.2,55.12) v1(36.2,54.36) v1(36.2,53.59) v1(36.2,52.83) v1(36.96,68.58) v1(36.96,67.82) v1(36.96,67.06) v1(36.96,66.29) v1(36.96,62.74) v1(36.96,61.98) v1(36.96,61.21) v1(36.96,60.45) v1(36.96,55.12) v1(36.96,54.36) v1(36.96,53.59) v1(36.96,52.83) v1(38.32,31.15) v1(38.32,30.01) v1(39.41,31.15) v1(39.41,30.01) v1(40.5,31.15) v1(40.5,30.01) v1(41.12,23.62) v1(41.12,22.6)
QBEXT: length 15.8
  TOP w0.203: 57.61,52.5 U8.A5
  TOP w0.381: P16.2 52.45,46.81 52.45,53.09 53.21,53.85 56.26,53.85 57.61,52.5
REG: length 34.8
  TOP w0.229: U4.7 72.33,66.35 71.97,66.71 C41.1
  TOP w0.508: C41.1 v1(69.76,66.71)
  L4_PWR w0.508: P27.3 70.36,46.84 70.36,53.34 68.83,54.86 68.83,58.42 69.76,59.35 v1(69.76,66.71)
S1: length 27.6
  TOP w0.508: R66.2 v1(88.69,70.06)
  L4_PWR w0.762: P40.2 75.44,54.36 78.99,54.36 88.39,63.75 88.39,65.28 89.41,66.29 89.41,69.34 v1(88.69,70.06)
SCL: length 283.8
  TOP w0.152: v1(54.48,47.76) 54.48,47.21 R22.2
  TOP w0.203: U13.2 21.14,25.62 R88.2 ; R37.1 v1(68.35,61.26)
  TOP w0.229: v1(87.38,18.92) 88.05,19.59 U6.A4 ; U3.A1 93.34,44.05 v1(93.34,43.82)
  TOP w0.254: R88.2 v1(22.63,26.06)
  TOP w0.305: R113.2 v1(20.07,18.72) R115.2
  L3_SIG w0.203: v1(93.34,43.82) 90.81,46.36 88.9,46.36 87.76,45.21 79.88,45.21 77.85,47.24 77.85,49.4 79.88,51.44 79.88,60.83 78.99,61.72 78.99,62.99 75.44,66.55 71.63,66.55 70.1,65.02 66.7,65.02 v1(64.36,62.68) 66.16,60.88 66.95,60.88 68.83,59 68.83,55.63 73.74,50.72 73.74,42.75 71.78,40.79 57.12,40.79 54.48,43.43 v1(54.48,47.76) ; v3(33.16,38.73) 32.63,38.73 32.13,38.23 32.13,36.12 31.06,35.05 25.15,35.05 24.64,34.54 v1(22.61,34.54)
  BOTTOM w0.203: 22.63,34.52 v1(22.61,34.54) ; v3(58.92,51.7) 58.92,51.05 57.02,49.15 55.88,49.15 v1(54.48,47.76) 53.47,46.74 53.47,42.04 52.2,40.77 49.28,40.77 48.77,41.28 48.77,49.02 47.24,50.55 38.1,50.55 34.72,47.17 34.72,42.92 R25.2 34.33,42.79 33.16,41.62 v3(33.16,38.73) ; R56.2 86.32,19.98 86.11,20.19 70.99,20.19 67.69,23.49 67.69,31.11 68.45,31.88 72.52,31.88 75.95,35.31 87.03,35.31 R79.1 90.32,40.07 90.32,42.24 90.49,42.41 R78.2 92.46,43.82 v1(93.34,43.82) ; v1(64.36,62.68) D4.C 66.84,62.68 C94.1 66.94,62.67 v1(68.35,61.26) 68.58,61.04 TP31.1
  BOTTOM w0.254: SCL.1 22.22,6.35 22.22,13.08 20.07,15.24 v1(20.07,18.72) 20.07,22.1 19.18,22.99 19.18,23.62 21.62,26.06 v1(22.63,26.06) 22.63,34.52 ; R56.2 87,19.3 v1(87.38,18.92)
SCL_EXT: length 37.8
  TOP w0.203: 16.24,26.22 16.44,26.02 U13.12
  TOP w0.305: 16.24,26.22 14.77,27.69 12.45,27.69 11.81,27.05 11.81,22.61 P15.8
  BOTTOM w0.305: SCL_EXT.1 10.79,5.33 12.45,5.33 15.11,8 15.11,11.68 16.51,13.08 16.51,19.18 14.35,21.34 P15.8
SDA: length 298.3
  TOP w0.152: R21.2 55.63,47.13 v1(55.63,47.76)
  TOP w0.203: R89.2 21.11,25.22 U13.1 ; v1(78.61,21.08) 78.61,19.05 79.25,18.41 86.11,18.41 86.32,18.63 R59.1 ; R86.1 v1(68.35,62.92)
  TOP w0.229: U3.B1 94.72,44.3 v1(94.49,44.07) ; R59.1 87.01,19.99 U6.A5
  TOP w0.254: R89.2 v1(22.63,24.74)
  TOP w0.305: R116.2 v1(21.59,18.72) R114.2
  L3_SIG w0.203: v3(33.66,38.73) 33.66,39.24 33.15,39.75 32.23,39.75 30.86,38.38 30.86,36.8 30.12,36.07 v1(24,36.07) ; v1(55.63,47.76) 55.63,43.69 57.66,41.66 70.99,41.66 72.64,43.31 72.64,50.29 67.82,55.12 67.82,57.66 63.3,62.18 63.3,63.25 v1(64.36,64.32) 65.02,64.98 65.02,68.33 66.55,69.85 78.74,69.85 80.01,68.58 80.01,62.23 81.28,60.96 81.28,51.31 79.12,49.15 79.12,47.62 80.62,46.13 87.4,46.13 88.52,47.24 91.31,47.24 v1(94.49,44.07)
  BOTTOM w0.203: TP20.1 68.43,62.84 v1(68.35,62.92) 68.35,63.98 68.01,64.33 C93.1 66.84,64.32 D3.C v1(64.36,64.32) ; v1(94.49,44.07) 94.49,44.06 R80.2 92.07,42.41 91.91,42.25 91.91,40.26 R81.1 91.95,38.44 91.95,36.12 90.39,34.57 76.98,34.57 73.03,30.61 69.3,30.61 68.58,29.89 68.58,24.13 71.63,21.08 v1(78.61,21.08) ; v3(59.32,51.7) 59.32,50.74 57.23,48.64 56.52,48.64 55.63,47.76 v1(55.63,47.76) 55.63,42.81 51.99,39.17 48.74,39.17 47.75,40.16 47.75,48.01 46.23,49.53 39.12,49.53 37.08,47.5 37.08,44.63 35.92,43.46 R58.2 36.1,42.79 37.59,41.3 37.59,40.79 37.39,40.59 34.24,40.59 33.66,40.01 v3(33.66,38.73)
  BOTTOM w0.254: v1(24,36.07) 24,25.15 23.59,24.74 v1(22.63,24.74) 21.59,23.7 v1(21.59,18.72) 21.59,15.88 23.75,13.72 23.75,7.24 25.15,5.84 28.45,5.84 SDA.1
SDA_EXT: length 32.5
  TOP w0.203: U13.13 16.44,25.62 16.24,25.42
  TOP w0.305: 16.24,25.42 14.08,25.42 P15.4
  BOTTOM w0.305: P15.4 15.49,24 15.49,22.35 17.91,19.94 17.91,12.32 16.26,10.67 16.26,7.47 12.45,3.66 SDA_EXT.1
SNS1N: length 20.5
  L2_GND w0.254: v2(90.9,19.99) 93.8,19.99 98.42,15.37 107.82,15.37 v1(108.33,15.88)
  BOTTOM w0.508: R39.2 v1(108.33,15.88)
SNS1P: length 20.5
  L2_GND w0.254: v2(90.9,19.59) 93.44,19.59 98.2,14.83 107.85,14.83 v1(108.33,14.35)
  BOTTOM w0.508: R38.2 v1(108.33,14.35)
SNS2P: length 20.6
  L2_GND w0.254: v1(72.26,14.22) 73.15,15.11 82.26,15.11 86.74,19.59 v2(89.7,19.59)
  BOTTOM w0.508: R40.2 v1(72.26,14.22)
SNS3N: length 20.5
  L2_GND w0.254: v2(89.7,20.39) 86.8,20.39 82.2,24.99 72.74,24.99 v1(72.26,24.51)
  BOTTOM w0.508: R42.2 v1(72.26,24.51)
SNS3P: length 20.5
  L2_GND w0.254: v2(89.7,20.79) 87.16,20.79 82.42,25.53 72.77,25.53 v1(72.26,26.04)
  BOTTOM w0.508: R41.2 v1(72.26,26.04)
SNS4P: length 20.5
  L2_GND w0.254: v2(90.9,20.79) 93.85,20.79 98.33,25.27 107.57,25.27 v1(108.33,26.04)
  BOTTOM w0.508: R43.2 v1(108.33,26.04)
THM: length 10.2
  TOP w0.508: v1(56.36,57.91) JP1.2 C16.1
  L3_SIG w0.203: v3(59.32,52.5) 59.04,52.5 58.29,53.24 58.29,55.98 v1(56.36,57.91)
U6_IN: length 5.8
  TOP w0.508: C37.1 v1(95.25,19.39)
  L2_GND w0.254: v1(95.25,19.39) 94.25,20.39 v2(90.9,20.39)
  vias: v1(89.15,27.94) v1(89.15,27.18) v1(89.15,13.21) v1(89.15,12.45) v1(89.92,27.94) v1(89.92,27.18) v1(89.92,13.21) v1(89.92,12.45) v1(90.68,27.94) v1(90.68,27.18) v1(90.68,13.21) v1(90.68,12.45) v1(91.44,27.94) v1(91.44,27.18) v1(91.44,13.21) v1(91.44,12.45)
UNNAMED_2_ADMAX147XX_I1_ENN: length 10.4
  TOP w0.203: v1(41.78,59.56) 42.32,59.03 P5.2 44.86,59.03 R6.2
  BOTTOM w0.203: v1(41.78,59.56) 41.15,59.56 39.37,57.79 36.83,57.79 36.63,57.98 v3(36.21,57.98)
UNNAMED_2_ADMAX147XX_I1_OTGEB: length 11.3
  TOP w0.203: U1.E5 37.18,58.38 37.72,58.93 38.35,58.93 39.37,59.94 41.4,59.94 41.91,60.45 41.91,61.85 42.14,62.08 P8.1 44.86,62.08 R12.1
UNNAMED_2_ADMAX147XX_I1_OTGENA: length 10.7
  TOP w0.203: R11.1 44.99,52.68 P7.1 42.32,52.68 37.81,57.19 U1.E2
UNNAMED_2_ADMAX147XX_I1_OVLOA: length 6.1
  BOTTOM w0.203: R1.1 36.07,57.02 35.81,57.28 v3(35.81,57.59)
UNNAMED_2_ADMAX147XX_I1_OVLOB: length 5.8
  BOTTOM w0.203: R2.1 40.32,57.4 36.4,57.4 v3(36.21,57.59)
UNNAMED_2_ADMAX147XX_I1_PCON: length 9.6
  TOP w0.203: R7.2 44.99,55.73 P6.2 41.3,55.73 39.44,57.59 U1.E3
UNNAMED_2_ADMAX173XXV2_I188_ALRT: length 2.7
  TOP w0.229: R34.1 72.33,61.66 73.13,62.46 U4.10
UNNAMED_2_ADMAX173XXV2_I188_BATT: length 7.6
  TOP w0.229: 74.93,67.82 74.8,67.82 73.93,66.95 U4.3
  TOP w0.508: 74.93,67.82 75.31,67.82 76.62,69.13 C39.2 76.84,69.13 R30.2 C40.1
UNNAMED_2_ADMAX173XXV2_I188_CHG: length 4.8
  TOP w0.229: v1(75.44,62.59) 75.06,62.59 74.73,62.91 U4.14
  BOTTOM w0.254: v1(75.44,62.59) 76.4,62.59 TP6.1 77.67,63.86 R35.1
UNNAMED_2_ADMAX173XXV2_I188_CP: length 3.4
  TOP w0.229: U4.2 74.33,66.59 74.68,66.93 75.06,66.93
  TOP w0.508: 75.06,66.93 76.24,66.93 C39.1
UNNAMED_2_ADMAX173XXV2_I188_DIS: length 6.2
  TOP w0.229: U4.12 73.93,62.16 v1(74.13,61.96)
  BOTTOM w0.254: R36.1 77.81,61.59 74.5,61.59 v1(74.13,61.96)
UNNAMED_2_ADMAX173XXV2_I188_PFAIL: length 3
  TOP w0.229: v1(73.79,67.69) 73.53,67.44 U4.4
  BOTTOM w0.508: R32.1 v1(73.79,67.69)
UNNAMED_2_ADMAX173XXV2_I188_SCL: length 2.9
  TOP w0.229: U4.9 72.73,62.75 72.29,62.31 72,62.31 R37.2
UNNAMED_2_ADMAX173XXV2_I188_SDA: length 1.8
  TOP w0.229: R86.2 71.08,62.79 72.16,62.79 72.33,62.96 U4.8
UNNAMED_2_ADMAX173XXV2_I188_TH: length 1.5
  TOP w0.203: U4.1 75.59,66.08 75.64,66.03 R31.2
UNNAMED_2_ADMAX173XXV2_I188_ZVC: length 2.9
  TOP w0.229: P9.2 75.03,61.95 74.33,62.65 U4.13
UNNAMED_2_ADMAX7778X_I78_BST: length 2.1
  BOTTOM w0.254: v3(59.72,51.7) 59.72,50.06 C20.1
UNNAMED_2_ADMAX7778X_I78_BYP1: length 8.1
  TOP w0.152: U8.C2 U8.C1
  TOP w0.229: C29.1 59.34,48.55 59.72,48.93 U8.C1
  TOP w0.508: C28.1 C25.1 58.89,47.48 C29.1
UNNAMED_2_ADMAX7778X_I78_DISQBAT: length 2.6
  BOTTOM w0.152: v3(60.12,52.5) 61.18,52.5 61.93,53.24 P36.1
UNNAMED_2_ADMAX7778X_I78_DN: length 5.5
  BOTTOM w0.15: R94.1 56.27,55.85 56.94,55.85 57.53,55.26 57.53,54.31 58.54,53.3 59.32,53.3 v3(59.32,53.3)
UNNAMED_2_ADMAX7778X_I78_DN1: length 5.1
  TOP w0.15: R90.2 56.27,55.85 56.94,55.85 57.53,55.26 57.53,54.31 58.54,53.3 58.92,53.3 U8.A7
UNNAMED_2_ADMAX7778X_I78_DP: length 5.5
  BOTTOM w0.15: R93.1 56.27,55.45 56.77,55.45 57.12,55.09 57.12,54.14 58.37,52.89 59.32,52.89 v3(59.32,52.9)
UNNAMED_2_ADMAX7778X_I78_DP1: length 5.1
  TOP w0.15: R26.2 56.27,55.45 56.77,55.45 57.12,55.09 57.12,54.14 58.37,52.89 58.92,52.89 U8.A6
UNNAMED_2_ADMAX7778X_I78_ENBST: length 6.6
  L3_SIG w0.102: 60.17,51.64 v3(59.72,52.1)
  L3_SIG w0.203: 60.17,51.64 60.17,51.38 58.17,49.38 v1(58.17,47.75)
  BOTTOM w0.203: v1(58.17,47.75) 58.55,47.37 58.55,46.85 58.65,46.75 R24.1
UNNAMED_2_ADMAX7778X_I78_EXTSM: length 22.2
  L3_SIG w0.203: v3(60.12,52.9) 60.12,55.96 56.52,59.56 56.52,61.34 53.09,64.77 v1(53.09,67.56)
  BOTTOM w0.254: R23.2 53.71,68.19 v1(53.09,67.56)
UNNAMED_2_ADMAX7778X_I78_IRQB: length 7.5
  L3_SIG w0.203: v1(56.67,47.12) 56.67,48.69 58.42,50.44 58.42,51.87 58.65,52.1 v3(59.32,52.1)
  BOTTOM w0.203: v1(56.67,47.12) 57.35,46.43 R28.2
UNNAMED_2_ADMAX7778X_I78_LX1: length 4.3
  TOP w0.152: U8.E1 U8.E2 U8.E3 ; U8.D3 U8.D2 U8.D1
  TOP w0.229: U8.E1 60.52,50.6 v1(60.99,50.14) ; U8.D1 60.12,50.29 v1(60.27,50.14)
  BOTTOM w0.508: C20.2 60.27,48.73 v1(60.27,48.72)
  vias: v1(60.27,49.43) v1(60.99,49.43) v1(60.99,48.72) v1(62.61,46.51) v1(62.61,45.8) v1(62.61,45.09) v1(62.61,44.37) v1(62.61,43.66) v1(63.32,46.51) v1(63.32,45.8) v1(63.32,45.09) v1(63.32,44.37) v1(63.32,43.66)
UNNAMED_2_ADMAX7778X_I78_STAT: length 10.9
  L3_SIG w0.203: v3(60.52,52.1) 60.71,52.28 60.71,56.21 58.32,58.6 58.32,60.15 v1(59,60.83)
  BOTTOM w0.203: P37.1 v1(59,60.83)
UNNAMED_2_ADMAX7778X_I78_SUSPND: length 2.4
  BOTTOM w0.152: P25.1 61.85,51.31 60.58,51.31 60.12,51.77 v3(60.12,52.1)
UNNAMED_2_ADMAX7778X_I78_VDD: length 4.3
  TOP w0.229: C19.1 59.72,56.62 U8.C7
UNNAMED_2_ADMAX7778X_I78_VIO: length 22.8
  TOP w0.229: v1(57.15,51.82) 57.79,51.82 58.06,52.1 U8.A4
  L4_PWR w0.508: P11.2 52.58,41.4 52.58,50.29 53.34,51.05 56.39,51.05 v1(57.15,51.82)
UNNAMED_2_CAP_I62_N1: length 3.1
  TOP w0.254: U2.A2 33.16,40.12 32.26,41.02 C10.1
UNNAMED_2_CAP_I65_N1: length 1.3
  BOTTOM w0.254: C9.1 35.13,38.73 v3(34.66,38.73)
UNNAMED_2_CN2P_I163_N2: length 7.4
  TOP w0.254: 36.7,38.86 36.57,38.73 U2.B6
  TOP w0.508: 36.7,38.86 39.28,38.86 C103.1 40.35,38.65 40.89,38.1 P13.2
UNNAMED_2_CN3P_I312_N1: length 2.7
  TOP w0.508: P16.1 51.04,42.58 R64.2
UNNAMED_2_CN3P_I312_N3: length 2.4
  BOTTOM w0.508: R65.2 P16.3
UNNAMED_2_DIOLED_I24_N: length 2.7
  TOP w0.203: v1(45.1,70.98) 45.1,71.49 DS1.C
  BOTTOM w0.152: U7.6 v1(45.1,70.98)
UNNAMED_2_DIOLED_I24_P: length 2
  TOP w0.508: DS1.A 45.85,73.81 v1(45.85,74.68)
  BOTTOM w0.508: R18.2 45.85,73.87 v1(45.85,74.68)
UNNAMED_2_DIOLED_I25_N: length 2.8
  TOP w0.203: DS2.C 43.8,71.24 v1(43.8,70.98)
  BOTTOM w0.152: U7.4 v1(43.8,70.98)
UNNAMED_2_DIOLED_I25_P: length 2
  TOP w0.508: DS2.A 43.05,73.81 v1(43.05,74.68)
  BOTTOM w0.508: R19.2 43.05,73.87 v1(43.05,74.68)
UNNAMED_2_DIOLED_I282_N: length 23.4
  TOP w0.508: v1(48.77,70.99) 48.77,71.98 DS3.C
  L3_SIG w0.152: v1(59,63.2) 60.4,63.2 61.98,64.77 61.98,68.33 60.96,69.34 56.13,69.34 55.37,70.1 49.66,70.1 v1(48.77,70.99)
  BOTTOM w0.203: P37.2 v1(59,63.2)
UNNAMED_2_DIOLED_I282_P: length 2
  TOP w0.508: DS3.A 48.77,73.81 v1(48.77,74.68)
  BOTTOM w0.508: R29.2 48.77,73.87 v1(48.77,74.68)
UNNAMED_2_ICMAX77958_I12_GPIO0: length 6.1
  TOP w0.203: v1(38.73,34.67) 37.34,34.67 35.16,36.85 U2.E6
  BOTTOM w0.254: TP1.1 v1(38.73,34.67)
UNNAMED_2_ICMAX77958_I12_GPIO1: length 5.2
  BOTTOM w0.203: v3(34.16,38.73) 34.16,39.62 34.67,40.13 TP9.1
UNNAMED_2_ICMAX77958_I12_GPIO2: length 7.6
  TOP w0.203: U2.E5 34.66,36.46 38.35,32.77 v1(38.73,32.77)
  BOTTOM w0.254: TP10.1 v1(38.73,32.77)
UNNAMED_2_ICMAX77958_I12_GPIO03: length 11
  L2_GND w0.152: v2(34.66,37.73) 34.66,37.73 34.92,37.47 34.92,36.7 38.35,33.27 40.13,33.27 v1(41.53,34.67)
  BOTTOM w0.254: TP11.1 v1(41.53,34.67)
UNNAMED_2_ICMAX77958_I12_GPIO4: length 9.5
  TOP w0.203: U2.E4 34.16,35.95 37.47,32.64 37.47,32 v1(36.32,30.86)
  BOTTOM w0.203: TP12.1 v1(36.32,30.86)
UNNAMED_2_ICMAX77958_I12_GPIO5: length 6.8
  TOP w0.203: U2.E3 33.66,35.43 v1(36.32,32.77)
  BOTTOM w0.203: TP13.1 v1(36.32,32.77)
UNNAMED_2_ICMAX77958_I12_GPIO7: length 12.2
  L2_GND w0.152: v1(33.43,30.86) 34.37,31.8 36.45,31.8 36.96,32.31 36.96,32.89 33.91,35.94 33.91,37.47 33.66,37.71 v2(33.66,37.73)
  BOTTOM w0.203: TP17.1 v1(33.43,30.86)
UNNAMED_2_ICMAX77958_I12_GPIO8: length 4.8
  BOTTOM w0.152: v3(34.16,38.23) 34.42,37.97 34.42,37.47
  BOTTOM w0.203: TP18.1 37.76,36.73 34.95,36.73 34.42,37.26 34.42,37.47
UNNAMED_2_ICMAX77958_I12_INTB: length 3.5
  TOP w0.254: U2.A1 32.66,39.58 32.35,39.89
  TOP w0.508: 32.35,39.89 31.28,40.96 R63.1
UNNAMED_2_ICMAX77958_I12_SCLM: length 2.4
  BOTTOM w0.152: 33.66,37.47 33.66,37.73 v3(33.16,38.23)
  BOTTOM w0.203: R8.2 32.97,36.42 33.66,37.11 33.66,37.47
UNNAMED_2_ICMAX77958_I12_SDAM: length 2
  BOTTOM w0.152: 34.04,37.47 34.04,37.85 33.66,38.22 v3(33.66,38.23)
  BOTTOM w0.203: R5.2 34.04,37.47
UNNAMED_2_MODUSB24P4PSHLD_I13_SH1:
  vias: v1(1.14,47.55) v1(1.14,36.63) v1(1.91,47.55) v1(1.91,36.63) v1(2.67,47.55) v1(2.67,36.63) v1(6.73,47.55) v1(6.73,36.63) v1(7.49,47.55) v1(7.49,36.63) v1(8.26,47.55) v1(8.26,36.63)
UNNAMED_2_NC2P_I36_N2: length 2.2
  TOP w0.203: P7.2 45.02,53.49 R13.1
UNNAMED_2_NC2P_I42_N2: length 2.2
  TOP w0.203: R14.1 45.15,62.89 P8.2
UNNAMED_2_NC2P_I46_N1: length 2.2
  TOP w0.203: R3.2 45.15,59.84 P5.1
UNNAMED_2_NC2P_I48_N1: length 2.2
  TOP w0.203: P6.1 45.02,56.54 R4.2
UNNAMED_2_NC3PJMPR_I301_A: length 2.4
  TOP w0.508: JP1.1 55.52,60.41 RT1.1
UNNAMED_2_NC3PJMPR_I301_B: length 2.4
  TOP w0.508: R20.1 57.2,60.49 JP1.3
UNNAMED_2_RES_I183_N2: length 26
  TOP w0.381: Q1.4 v1(98.05,66.67)
  BOTTOM w0.254: R35.2 80.25,66.15 86.23,72.14 92.58,72.14 97.63,67.09 97.64,67.09 v1(98.05,66.67)
UNNAMED_2_RES_I295_N1: length 2.5
  TOP w0.508: v1(50.99,71.96) 50.99,72.99 S2.1
  BOTTOM w0.508: R23.1 v1(50.99,71.96)
UNNAMED_3_ADMAX77542_I19_ALTIN: length 23.8
  BOTTOM w0.254: v3(90.5,20.39) 91.89,20.39 91.95,20.45 95.72,20.45 C32.1
  BOTTOM w0.508: ALT_IN.1 107.95,20.19 97.16,20.19 96.48,20.87 C32.1
UNNAMED_3_ADMAX77542_I19_BST1: length 23.9
  TOP w0.229: v1(92.46,18.92) 92.19,19.19 U6.F3
  L3_SIG w0.508: 91.82,6.86 96.14,6.86 97.41,8.13 97.41,15.37 96.08,16.7 94.17,16.7 92.46,18.41 v1(92.46,18.92) ; 91.82,6.86 v1(91.06,7.62) v1(91.06,6.86) 91.82,6.86
UNNAMED_3_ADMAX77542_I19_BST2: length 23.7
  TOP w0.229: U6.A3 88.41,19.19 v1(88.14,18.92)
  L3_SIG w0.508: 88.77,6.86 v1(89.53,7.62) v1(89.53,6.86) 88.77,6.86 ; 88.77,6.86 85.22,6.86 83.06,9.02 83.06,15.37 84.26,16.57 86.3,16.57 88.14,18.41 v1(88.14,18.92)
UNNAMED_3_ADMAX77542_I19_BST3: length 23.5
  TOP w0.229: v1(88.14,21.46) 88.41,21.19 U6.A8
  L3_SIG w0.508: 88.77,33.53 v1(89.53,32.77) v1(89.53,33.53) 88.77,33.53 ; 88.77,33.53 85.22,33.53 83.06,31.37 83.06,25.27 84.2,24.13 85.98,24.13 88.14,21.97 v1(88.14,21.46)
UNNAMED_3_ADMAX77542_I19_BST4: length 23.6
  TOP w0.229: U6.F8 92.19,21.19 v1(92.46,21.46)
  L3_SIG w0.508: 91.82,33.53 v1(91.06,33.53) v1(91.06,32.77) 91.82,33.53 ; 91.82,33.53 95.38,33.53 97.54,31.37 97.54,25.15 96.52,24.13 94.62,24.13 92.46,21.97 v1(92.46,21.46)
UNNAMED_3_ADMAX77542_I19_IN11: length 6
  TOP w0.229: R68.1 90.5,16.4 v2(90.5,18.39) v2(90.5,18.79)
  L2_GND w0.229: v2(90.5,18.79) v2(90.5,18.39) 90.5,16.44 v2(90.81,16.13)
  vias: v2(90.81,15.62) v2(91.31,16.13) v2(91.31,15.62)
UNNAMED_3_ADMAX77542_I19_IN21: length 6
  TOP w0.229: R73.1 90.1,16.4 v2(90.1,18.39) v2(90.1,18.79)
  L2_GND w0.229: v2(90.1,18.79) v2(90.1,18.39) 90.1,16.44 v2(89.79,16.13)
  vias: v2(89.28,16.13) v2(89.28,15.62) v2(89.79,15.62)
UNNAMED_3_ADMAX77542_I19_IN31: length 6
  TOP w0.229: v2(90.1,21.59) v2(90.1,21.99) 90.1,23.99 R74.1
  L2_GND w0.229: v2(90.1,21.59) v2(90.1,21.99) 90.1,23.95 v2(89.79,24.26)
  vias: v2(89.28,24.76) v2(89.28,24.26) v2(89.79,24.76)
UNNAMED_3_ADMAX77542_I19_IN41: length 6
  TOP w0.229: v2(90.5,21.59) v2(90.5,21.99) 90.5,23.99 R75.1
  L2_GND w0.229: v2(90.5,21.59) v2(90.5,21.99) 90.5,23.95 v2(90.81,24.26)
  vias: v2(90.81,24.76) v2(91.31,24.76) v2(91.31,24.26)
UNNAMED_3_ADMAX77542_I19_LX11: length 13.4
  TOP w0.229: v2(90.9,18.79) v2(90.9,18.39) 90.9,17.69 92.2,16.38 92.2,11.04 v2(93.21,10.03) v2(93.72,9.53)
  L2_GND w0.229: v2(90.9,18.79) v2(90.9,18.39) 90.9,17.69 92.2,16.38
  vias: v2(91.19,17.78) v2(91.55,17.42) v2(91.9,17.06) v2(92.26,16.7) v2(92.26,15.69) v2(92.26,14.16) v2(92.26,12.64) v2(92.26,11.11) v2(92.67,17.06) v2(92.7,10.03) v2(92.7,9.53) v2(92.7,9.02) v2(93.03,16.7) v2(93.21,9.53) v2(93.21,9.02) v2(93.73,13.59) v2(93.73,11.81) v2(93.72,10.03) v2(93.72,9.02) v2(93.91,15.69) v2(94.23,10.03) v2(94.23,9.53) v2(94.23,9.02) v2(94.74,10.03) v2(94.74,9.53) v2(94.74,9.02) v2(95.06,14.16) v2(95.06,12.64) v2(95.06,11.11)
UNNAMED_3_ADMAX77542_I19_LX21: length 13.4
  TOP w0.229: v2(86.87,9.53) v2(87.38,10.03) 88.39,11.04 88.39,16.38 89.7,17.69 v2(89.7,18.39) v2(89.7,18.79)
  L2_GND w0.229: 88.39,16.38 89.7,17.69 v2(89.7,18.39) v2(89.7,18.79)
  vias: v2(85.54,14.16) v2(85.54,12.64) v2(85.54,11.11) v2(85.86,10.03) v2(85.86,9.53) v2(85.86,9.02) v2(86.37,10.03) v2(86.37,9.53) v2(86.37,9.02) v2(86.68,15.69) v2(86.87,13.59) v2(86.87,11.81) v2(86.87,10.03) v2(86.87,9.02) v2(87.38,9.53) v2(87.38,9.02) v2(87.57,16.7) v2(87.93,17.06) v2(87.89,10.03) v2(87.89,9.53) v2(87.89,9.02) v2(88.33,16.7) v2(88.33,15.69) v2(88.33,14.16) v2(88.33,12.64) v2(88.33,11.11) v2(88.69,17.06) v2(89.05,17.42) v2(89.41,17.78)
UNNAMED_3_ADMAX77542_I19_LX31: length 13.4
  TOP w0.229: v2(89.7,21.59) v2(89.7,21.99) 89.7,22.7 88.39,24 88.39,29.34 v2(87.38,30.35) v2(86.87,30.86)
  L2_GND w0.229: 88.39,24 89.7,22.7 v2(89.7,21.99) v2(89.7,21.59)
  vias: v2(85.54,29.27) v2(85.54,27.75) v2(85.54,26.22) v2(85.86,31.37) v2(85.86,30.86) v2(85.86,30.35) v2(86.37,31.37) v2(86.37,30.86) v2(86.37,30.35) v2(86.68,24.7) v2(86.87,31.37) v2(86.87,30.35) v2(86.87,28.57) v2(86.87,26.8) v2(87.38,31.37) v2(87.38,30.86) v2(87.57,23.68) v2(87.89,31.37) v2(87.89,30.86) v2(87.89,30.35) v2(87.93,23.32) v2(88.33,29.27) v2(88.33,27.75) v2(88.33,26.22) v2(88.33,24.7) v2(88.33,23.68) v2(88.69,23.32) v2(89.05,22.97) v2(89.41,22.61)
UNNAMED_3_ADMAX77542_I19_LX41: length 13.4
  TOP w0.229: v2(90.9,21.59) v2(90.9,21.99) 90.9,22.7 92.2,24 92.2,29.34 v2(93.21,30.35) v2(93.72,30.86)
  L2_GND w0.229: v2(90.9,21.59) v2(90.9,21.99) 90.9,22.7 92.2,24
  vias: v2(91.19,22.61) v2(91.55,22.97) v2(91.9,23.32) v2(92.26,29.27) v2(92.26,27.75) v2(92.26,26.22) v2(92.26,24.7) v2(92.26,23.68) v2(92.7,31.37) v2(92.7,30.86) v2(92.7,30.35) v2(92.67,23.32) v2(93.03,23.68) v2(93.21,31.37) v2(93.21,30.86) v2(93.72,31.37) v2(93.72,30.35) v2(93.73,28.57) v2(93.73,26.8) v2(93.91,24.7) v2(94.23,31.37) v2(94.23,30.86) v2(94.23,30.35) v2(94.74,31.37) v2(94.74,30.86) v2(94.74,30.35) v2(95.06,29.27) v2(95.06,27.75) v2(95.06,26.22)
UNNAMED_3_ADMAX77542_I19_VL12: length 4.5
  TOP w0.229: v1(93.22,18.92) 92.55,19.59 U6.F4
  BOTTOM w0.254: v1(93.22,18.92) 93.69,18.92 C46.1
UNNAMED_3_ADMAX77542_I19_VL34: length 4.5
  TOP w0.229: v1(93.22,21.46) 92.55,20.79 U6.F7
  BOTTOM w0.254: C43.1 93.69,21.46 v1(93.22,21.46)
UNNAMED_3_ADMAX77542_I31_CFG1: length 4.2
  BOTTOM w0.254: v3(90.1,19.99) 87.41,19.99 R54.2
UNNAMED_3_ADMAX77542_I31_CFG2: length 6.3
  BOTTOM w0.254: R49.2 95.67,19.94 91.95,19.94 91.89,19.99 v3(90.5,19.99)
UNNAMED_3_ADMAX77542_I31_IRQB: length 8.8
  L2_GND w0.254: v2(89.7,19.99) 82.73,19.99 v1(82.17,19.43)
  BOTTOM w0.203: R60.1 v1(82.17,19.43)
UNNAMED_3_ADMAX77542_I31_MFIO1: length 5.5
  BOTTOM w0.203: R15.1 93,16.22 90.9,18.32 v3(90.9,19.19)
UNNAMED_3_ADMAX77542_I31_MFIO2: length 3.5
  BOTTOM w0.203: v3(90.5,19.19) 90.5,17.83 91.31,17.02 TP23.1
UNNAMED_3_ADMAX77542_I31_MFIO3: length 5.6
  BOTTOM w0.203: R47.1 89.6,15.72 89.6,17.34 90.1,17.83 v3(90.1,19.19)
UNNAMED_3_ADMAX77542_I31_MFIO4: length 4.1
  BOTTOM w0.203: TP25.1 89.7,18.2 v3(89.7,19.19)
UNNAMED_3_ADMAX77542_I31_MFIO5: length 5.5
  BOTTOM w0.203: R70.1 88.23,23.03 89.7,21.55 v3(89.7,21.19)
UNNAMED_3_ADMAX77542_I31_MFIO6: length 3.5
  BOTTOM w0.203: TP27.1 89.41,23.24 90.1,22.55 v3(90.1,21.19)
UNNAMED_3_ADMAX77542_I31_MFIO7: length 5.6
  BOTTOM w0.203: v3(90.5,21.19) 90.5,23.31 92.37,25.19 R85.1
UNNAMED_3_ADMAX77542_I31_MFIO8: length 2.4
  BOTTOM w0.203: v3(90.9,21.19) 90.9,22.06 TP29.1
UNNAMED_3_ADMAX77542_I31_SEL1: length 6.2
  BOTTOM w0.254: v3(90.5,19.59) 91.57,19.59 91.82,19.34 91.82,18.67 94.36,16.13 R46.1
